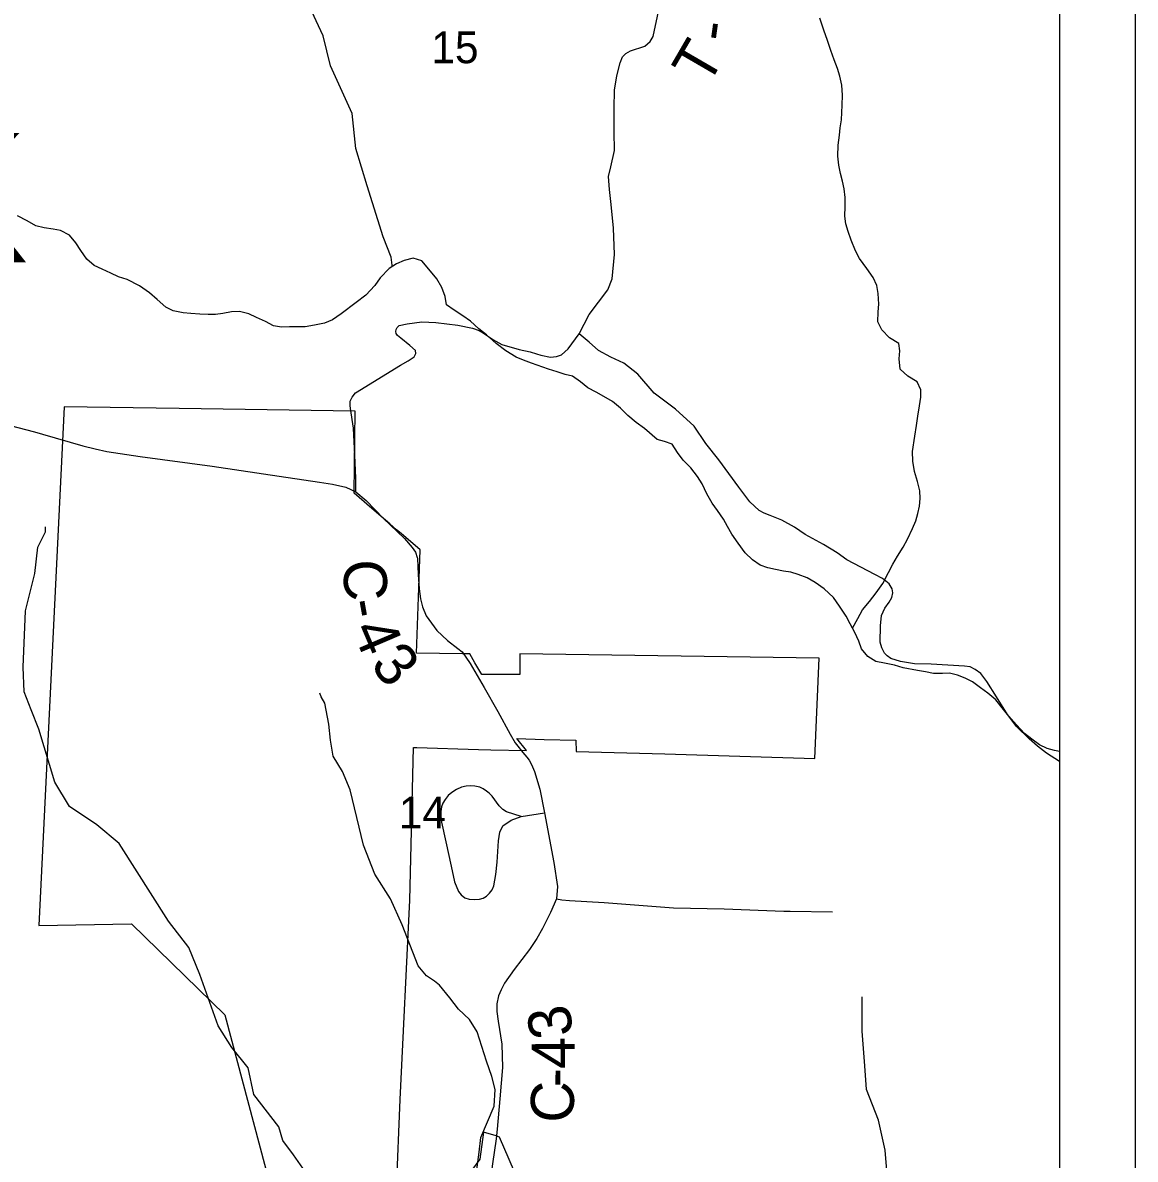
# Model space of a CAD drawing. Extents: x 0 to 34, y 0 to 22.
# Drawn here: x 7.533 to 9, y 16.768 to 18.266 of the extents above; entities that cross this region are included whole.
import ezdxf

# ---------------------------------------------------------------- set-up
doc = ezdxf.new("R2010")
doc.units = 0
for name, color, linetype in [('GM_X_Corporation', 7, 'Continuous'), ('GM_X_County_Road', 7, 'Continuous'), ('GM_X_County_Road_Text', 7, 'Continuous'), ('GM_X_Minor_River', 7, 'Continuous'), ('GM_X_Section_Text', 7, 'Continuous'), ('GM_X_Township_Road', 7, 'Continuous'), ('GM_X_Township_Road_Text', 7, 'Continuous'), ('GM_X_Township_Text', 7, 'Continuous'), ('SH_Data', 7, 'Continuous')]:
    doc.layers.add(name, color=color, linetype=linetype)

msp = doc.modelspace()

# ---------------------------------------------------------------- linework, layer by layer
at = {"layer": 'GM_X_Corporation'}
for points in [[(8.026, 16.7284), (8.0309, 16.847), (8.0435, 17.1098), (8.0484, 17.311), (8.0528, 17.3109), (8.1339, 17.3081), (8.1505, 17.3078), (8.1972, 17.3069), (8.1847, 17.3227), (8.2207, 17.3215), (8.2624, 17.3207), (8.2627, 17.3056), (8.3795, 17.3025), (8.5775, 17.2962), (8.5832, 17.4288), (8.1885, 17.4343), (8.1885, 17.407), (8.1382, 17.407), (8.1292, 17.4224), (8.1225, 17.4344), (8.1131, 17.4344), (8.0522, 17.4352), (8.0553, 17.5214), (8.0572, 17.5712), (8.0319, 17.5929), (8.0261, 17.5978), (8.0171, 17.6056), (8.0114, 17.6104), (7.9934, 17.6258), (7.9699, 17.646), (7.9714, 17.7543), (7.7392, 17.7577), (7.5878, 17.7599), (7.5545, 17.0763), (7.6764, 17.0783), (7.7995, 16.9584), (7.8613, 16.7271)], [(8.1943, 16.7219), (8.1619, 16.7973), (8.1571, 16.7989), (8.1408, 16.804), (8.1357, 16.7683), (8.1043, 16.7251)]]:
    msp.add_lwpolyline(points, dxfattribs=at)
at = {"layer": 'GM_X_County_Road'}
for points in [[(7.5164, 17.7354), (7.5485, 17.7269), (7.5591, 17.7239)], [(7.5591, 17.7239), (7.6124, 17.7086), (7.6286, 17.7043), (7.644, 17.701), (7.6881, 17.6944), (7.7827, 17.6817), (7.8504, 17.6714), (7.9245, 17.6608), (7.9415, 17.6579), (7.9592, 17.6538), (7.9724, 17.6478)], [(7.9724, 17.6478), (7.986, 17.6362), (8.0089, 17.6129), (8.0366, 17.5863), (8.0465, 17.5746), (8.0511, 17.5683), (8.0532, 17.5613)], [(8.0532, 17.5613), (8.0535, 17.5603), (8.0543, 17.5389), (8.0556, 17.5201), (8.0575, 17.5066), (8.0604, 17.4961), (8.0649, 17.4844), (8.0789, 17.4651), (8.0931, 17.4521), (8.1068, 17.4412)], [(8.1068, 17.4412), (8.1125, 17.4368), (8.123, 17.4215), (8.1417, 17.3898), (8.1597, 17.3582), (8.1758, 17.3284), (8.1823, 17.3169), (8.1841, 17.3147)], [(8.1841, 17.3147), (8.1926, 17.3042), (8.1979, 17.2983), (8.2007, 17.2942), (8.2041, 17.2885), (8.2079, 17.2794), (8.215, 17.2559), (8.221, 17.2247)], [(8.221, 17.2247), (8.2333, 17.1591), (8.2383, 17.1278), (8.2367, 17.1116), (8.229, 17.0933), (8.2184, 17.0724), (8.211, 17.0593), (8.2011, 17.0448), (8.1811, 17.0183), (8.1684, 17.0001), (8.1639, 16.9915), (8.1604, 16.9834), (8.1584, 16.9732), (8.1583, 16.9629), (8.16, 16.9503), (8.165, 16.92), (8.1656, 16.8891), (8.1623, 16.8476), (8.1588, 16.8079), (8.1571, 16.795)], [(8.1571, 16.795), (8.1527, 16.7621), (8.1504, 16.7449), (8.1501, 16.7257), (8.1528, 16.7071), (8.1555, 16.6954)]]:
    msp.add_lwpolyline(points, dxfattribs=at)
at = {"layer": 'GM_X_Minor_River'}
for points in [[(8.02, 17.9448), (8.0201, 17.9468), (8.0188, 17.9571), (8.0085, 17.9839), (7.9873, 18.0512), (7.9724, 18.1004), (7.9674, 18.1467), (7.9391, 18.2093), (7.9293, 18.2487), (7.8838, 18.3465)], [(8.627, 17.4683), (8.6343, 17.4809), (8.6404, 17.4921), (8.6496, 17.5034), (8.6583, 17.5147), (8.6671, 17.5271), (8.6746, 17.5414), (8.6804, 17.5523), (8.6865, 17.5631), (8.6941, 17.5751), (8.6998, 17.5856), (8.7062, 17.5995), (8.7105, 17.6095), (8.7132, 17.6191), (8.7156, 17.629), (8.7164, 17.6389), (8.7161, 17.6492), (8.7127, 17.6616), (8.7088, 17.6748), (8.7065, 17.6881), (8.7061, 17.701), (8.7093, 17.7212), (8.7115, 17.7354), (8.7134, 17.7476), (8.7153, 17.761), (8.7172, 17.7724), (8.7173, 17.7823), (8.7124, 17.7928), (8.7003, 17.8001), (8.6898, 17.8096), (8.6886, 17.8233), (8.6894, 17.8336), (8.6883, 17.8434), (8.676, 17.8507), (8.6657, 17.8614), (8.6605, 17.8719), (8.6612, 17.8852), (8.662, 17.8951), (8.6612, 17.9092), (8.6594, 17.9197), (8.6545, 17.9302), (8.6461, 17.9422), (8.6366, 17.9556), (8.6313, 17.9653), (8.6255, 17.9796), (8.6214, 17.9908), (8.6184, 18.001), (8.617, 18.0112), (8.6173, 18.0238), (8.6173, 18.036), (8.6162, 18.0473), (8.614, 18.0575), (8.6114, 18.0674), (8.6092, 18.0783), (8.6076, 18.0901), (8.6083, 18.1049), (8.6102, 18.1179), (8.611, 18.1278), (8.6126, 18.1381), (8.6131, 18.1477), (8.6135, 18.1576), (8.6139, 18.1705), (8.6131, 18.1838), (8.6104, 18.1959), (8.6075, 18.2057), (8.6029, 18.2173), (8.5984, 18.2294), (8.5941, 18.2426), (8.5895, 18.2565), (8.5841, 18.2723)], [(8.3309, 17.7483), (8.3211, 17.7579), (8.3106, 17.7671), (8.2993, 17.7736), (8.2893, 17.7794), (8.2781, 17.7851), (8.2683, 17.7928), (8.2578, 17.8001), (8.2483, 17.8024), (8.2379, 17.8059), (8.2264, 17.8097), (8.2037, 17.8174), (8.1933, 17.8213), (8.1837, 17.8255), (8.1701, 17.8335), (8.1573, 17.8433), (8.1447, 17.8547), (8.1346, 17.8628), (8.1236, 17.8727), (8.1132, 17.88), (8.1019, 17.8873), (8.0918, 17.8942), (8.0899, 17.9055), (8.0858, 17.9172), (8.0789, 17.9284), (8.0687, 17.9414), (8.0592, 17.9521), (8.048, 17.9559), (8.036, 17.9529), (8.0259, 17.9484), (8.0162, 17.9424), (8.0044, 17.9299), (7.9975, 17.9198), (7.9853, 17.9072), (7.9727, 17.8973), (7.953, 17.8826), (7.9415, 17.8747), (7.931, 17.8702), (7.9178, 17.8675), (7.9053, 17.8652), (7.8847, 17.8653), (7.8741, 17.865), (7.8638, 17.8666), (7.853, 17.8723), (7.8414, 17.8776), (7.831, 17.8823), (7.8187, 17.8857), (7.8085, 17.885), (7.7971, 17.8827), (7.7873, 17.8817), (7.7774, 17.8814), (7.7668, 17.8818), (7.7549, 17.8829), (7.7446, 17.8838), (7.7316, 17.8864), (7.7216, 17.8914), (7.7103, 17.9013), (7.7001, 17.9101), (7.6869, 17.9192), (7.6706, 17.9279), (7.6595, 17.9313), (7.6491, 17.9359), (7.6379, 17.9413), (7.6271, 17.9463), (7.6174, 17.9543), (7.6098, 17.9659), (7.603, 17.9759), (7.5947, 17.9863), (7.5827, 17.9924), (7.5731, 17.994), (7.5613, 17.9956), (7.5502, 17.9983), (7.539, 18.0051), (7.5262, 18.0116)], [(8.9, 17.3058), (8.8937, 17.3071), (8.8837, 17.3095), (8.8737, 17.3145), (8.8636, 17.3218), (8.8538, 17.3295), (8.8432, 17.3409), (8.8334, 17.352), (8.8243, 17.3632), (8.816, 17.3735), (8.8058, 17.3824), (8.7961, 17.3893), (8.7852, 17.3973), (8.7755, 17.4023), (8.7655, 17.4062), (8.7552, 17.4089), (8.7457, 17.4086), (8.7339, 17.4086), (8.7232, 17.4106), (8.7129, 17.4122), (8.6941, 17.4158), (8.6826, 17.4192), (8.6692, 17.4222), (8.6578, 17.4242), (8.6473, 17.4307), (8.639, 17.4407), (8.6356, 17.4512), (8.6303, 17.4625), (8.6239, 17.4737), (8.6186, 17.4838), (8.6102, 17.4972), (8.6019, 17.5084), (8.5897, 17.5202), (8.5781, 17.5285), (8.5672, 17.5343), (8.5557, 17.5389), (8.5457, 17.542), (8.5362, 17.5432), (8.5258, 17.5456), (8.5155, 17.5475), (8.5055, 17.551), (8.4954, 17.5583), (8.4856, 17.5675), (8.4765, 17.5802), (8.4681, 17.5921), (8.4625, 17.6022), (8.4569, 17.6119), (8.4493, 17.6234), (8.4421, 17.6331), (8.4353, 17.6451), (8.4288, 17.6582), (8.4228, 17.6682), (8.4141, 17.6794), (8.4039, 17.6897), (8.3963, 17.6998), (8.3895, 17.7106), (8.3791, 17.7144), (8.3695, 17.7168), (8.3531, 17.7311), (8.3419, 17.7391), (8.3309, 17.7483)], [(7.9022, 16.7563), (7.8901, 16.774), (7.8762, 16.7928), (7.8709, 16.8109), (7.8377, 16.8537), (7.8302, 16.8886), (7.809, 16.9156), (7.7907, 16.9442), (7.7664, 17.0118), (7.7522, 17.0473), (7.7255, 17.0818), (7.6602, 17.1842), (7.631, 17.2088), (7.5947, 17.2329), (7.5756, 17.2652), (7.5543, 17.3348), (7.544, 17.3605), (7.5349, 17.3843), (7.5336, 17.4166), (7.5368, 17.4911), (7.5491, 17.54), (7.553, 17.575), (7.5633, 17.5953), (7.5632, 17.6018)], [(8.1219, 16.6783), (8.135, 16.7776), (8.1373, 16.7966), (8.1547, 16.8379), (8.1562, 16.86), (8.1517, 16.8774), (8.1446, 16.8975), (8.1322, 16.936), (8.1221, 16.9522), (8.1075, 16.966), (8.0962, 16.9811), (8.0827, 16.9976), (8.0762, 17.0028), (8.0655, 17.0098), (8.0543, 17.0229), (8.0333, 17.0773), (8.0179, 17.1113), (7.9973, 17.144), (7.9826, 17.1822), (7.9647, 17.2552), (7.9545, 17.2794), (7.9424, 17.2993), (7.939, 17.3206), (7.9367, 17.3414), (7.9313, 17.3695), (7.9266, 17.3778), (7.9247, 17.3823)], [(8.6735, 16.7426), (8.6702, 16.7801), (8.6616, 16.8195), (8.6457, 16.8599), (8.6433, 16.8911), (8.6398, 16.937), (8.6401, 16.9655), (8.6398, 16.9822)]]:
    msp.add_lwpolyline(points, dxfattribs=at)
at = {"layer": 'GM_X_Township_Road'}
msp.add_line((8.545, 17.0952), (8.6008, 17.0944), dxfattribs=at)
for points in [[(8.2107, 17.8298), (8.2164, 17.8281), (8.229, 17.8253), (8.237, 17.826), (8.2434, 17.8283), (8.2521, 17.8365), (8.2668, 17.8559), (8.2801, 17.8817), (8.3047, 17.9143), (8.3102, 17.9286), (8.3132, 17.9605), (8.312, 17.9953), (8.3088, 18.0267), (8.3067, 18.0464), (8.3053, 18.0633), (8.3083, 18.0764), (8.3132, 18.0978), (8.3128, 18.1222), (8.3127, 18.1536), (8.3135, 18.1771), (8.3166, 18.1961), (8.3207, 18.2131), (8.3237, 18.2213), (8.3281, 18.2254), (8.3345, 18.2291), (8.3535, 18.2353), (8.3605, 18.2412), (8.3644, 18.248), (8.3739, 18.2934)], [(7.9652, 17.7575), (7.9646, 17.7615), (7.9647, 17.7673), (7.9673, 17.7728), (7.9719, 17.7784), (8.0313, 17.8146), (8.0414, 17.8205), (8.0493, 17.8259), (8.0515, 17.83), (8.051, 17.8341), (8.0434, 17.8408), (8.0318, 17.8504), (8.0274, 17.8539), (8.0255, 17.8567), (8.0249, 17.859), (8.0254, 17.8617), (8.0268, 17.8644), (8.0296, 17.8669), (8.04, 17.8692), (8.0592, 17.8719), (8.0778, 17.871), (8.1068, 17.8673), (8.1262, 17.8636), (8.1348, 17.8605), (8.1401, 17.8573), (8.1528, 17.8486), (8.1648, 17.842), (8.1877, 17.8355), (8.2022, 17.8323), (8.2107, 17.8298)], [(8.9, 17.2922), (8.8831, 17.3032), (8.871, 17.3125), (8.86, 17.3224), (8.8434, 17.3385), (8.8317, 17.3545), (8.8169, 17.3778), (8.8042, 17.3978), (8.7963, 17.4083), (8.7888, 17.4137), (8.7823, 17.417), (8.7747, 17.4181), (8.7307, 17.4205), (8.7089, 17.4212), (8.6905, 17.4244), (8.6775, 17.428), (8.6728, 17.4315), (8.6695, 17.4351), (8.6659, 17.4421), (8.6638, 17.4495), (8.664, 17.471), (8.6654, 17.485), (8.6696, 17.4944), (8.6754, 17.5023), (8.6788, 17.5087), (8.6802, 17.5148), (8.6794, 17.5199), (8.6753, 17.5264), (8.6669, 17.5335), (8.6568, 17.539), (8.6198, 17.5581), (8.6069, 17.5675), (8.5887, 17.5783), (8.5646, 17.5917), (8.5506, 17.6014), (8.5339, 17.6104), (8.5184, 17.6167), (8.5107, 17.6198), (8.5043, 17.6234), (8.4917, 17.6348), (8.4771, 17.654), (8.4511, 17.69), (8.4339, 17.7117), (8.4184, 17.7343), (8.3938, 17.7566), (8.3657, 17.7779), (8.3439, 17.803), (8.3257, 17.8173), (8.3084, 17.8255), (8.2922, 17.8342), (8.2798, 17.8453), (8.2668, 17.8559)], [(7.9724, 17.6478), (7.9725, 17.6657), (7.9709, 17.6961), (7.969, 17.7318), (7.9652, 17.7575)], [(8.1904, 17.2199), (8.1711, 17.2259), (8.1661, 17.2293), (8.1613, 17.2338), (8.1522, 17.2466), (8.1483, 17.2506), (8.1447, 17.2535), (8.1403, 17.2564), (8.1357, 17.2585), (8.1294, 17.2598), (8.1236, 17.2603), (8.1178, 17.26), (8.1117, 17.2584), (8.105, 17.2554), (8.0989, 17.2515), (8.0942, 17.2475), (8.09, 17.2424), (8.0872, 17.2375), (8.0854, 17.2326), (8.0842, 17.2267), (8.0842, 17.2202), (8.0852, 17.2126), (8.091, 17.1866), (8.0979, 17.1546), (8.1025, 17.1337), (8.1075, 17.1212), (8.111, 17.1167), (8.1158, 17.1128), (8.1219, 17.1111), (8.1294, 17.1104), (8.1354, 17.1109), (8.1403, 17.1124), (8.1447, 17.1151), (8.1484, 17.1188), (8.152, 17.1232), (8.1544, 17.1285), (8.157, 17.1436), (8.1588, 17.1597), (8.1605, 17.1878), (8.1621, 17.1993), (8.1663, 17.2078), (8.177, 17.2152), (8.1904, 17.2199), (8.221, 17.2247)], [(8.2367, 17.1116), (8.2439, 17.1099), (8.2539, 17.109), (8.2997, 17.1066), (8.391, 17.0997), (8.4581, 17.098), (8.5366, 17.0953), (8.545, 17.0952)]]:
    msp.add_lwpolyline(points, dxfattribs=at)
at = {"layer": 'SH_Data'}
msp.add_line((9, 21), (9, 14), dxfattribs=at)
msp.add_lwpolyline([(2.1, 20.9), (8.9, 20.9), (8.9, 14.1), (2.1, 14.1)], close=True, dxfattribs=at)

# ---------------------------------------------------------------- texts
at = {"layer": 'GM_X_County_Road_Text'}
for s, rotation, p in [('C', 272.7018, (7.9552, 17.5576)), ('-', 280.1308, (7.9583, 17.503)), ('4', 293.1205, (7.9665, 17.4666)), ('3', 310.1476, (7.9898, 17.4188)), ('3', 100.119, (8.2598, 16.9331)), ('4', 90.1632, (8.2608, 16.8873)), ('-', 88.9286, (8.2604, 16.8627)), ('C', 88.6221, (8.2592, 16.8157))]:
    msp.add_text(s, height=0.0568, rotation=rotation, dxfattribs=at).set_placement(p)
at = {"layer": 'GM_X_Section_Text'}
for s, p in [('15', (8.0718, 18.2128)), ('14', (8.0289, 17.2043))]:
    msp.add_text(s, height=0.04186, rotation=0, dxfattribs=at).set_placement(p)
at = {"layer": 'GM_X_Township_Road_Text'}
for s, rotation, p in [('-', 81.9377, (8.4652, 18.2399)), ('T', 59.8697, (8.4361, 18.1807))]:
    msp.add_text(s, height=0.0568, rotation=rotation, dxfattribs=at).set_placement(p)
at = {"layer": 'GM_X_Township_Text'}
msp.add_text('CREEK', height=0.17045, rotation=0, dxfattribs=at).set_placement((6.7547, 17.9503))

doc.saveas('drawing.dxf')
